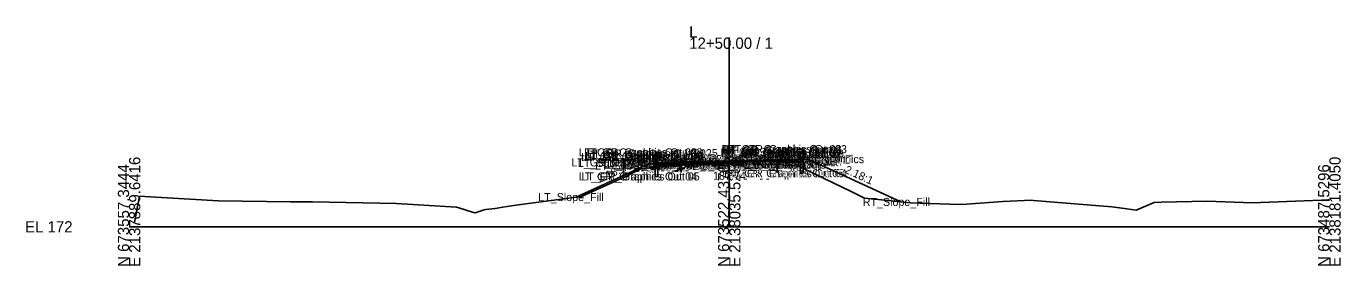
# Model space of a CAD drawing. Extents: x -26 to 5503, y -10 to 7033.
# Drawn here: x -25.7 to 302.8, y 3490.3 to 3550 of the extents above; entities that cross this region are included whole.
import ezdxf

# ---------------------------------------------------------------- set-up
doc = ezdxf.new("R2010")
doc.units = 0
for name, color, linetype in [('Default', 7, 'Continuous'), ('Exist CMT Pavement', 7, 'Continuous'), ('Exist Cross Section Cell', 7, 'Continuous'), ('Exist XS Center Line Elevation Label', 7, 'Continuous'), ('Exist XS Ground Line', 7, 'Continuous'), ('Prop CMT Guardrail Graphics', 7, 'Continuous'), ('Prop CMT Pvmt Course 1', 7, 'Continuous'), ('Prop CMT Pvmt Course 1 Wedge', 7, 'Continuous'), ('Prop CMT Pvmt Course 2', 7, 'Continuous'), ('Prop CMT Pvmt Course 2 Wedge', 7, 'Continuous'), ('Prop CMT Pvmt Course 3', 7, 'Continuous'), ('Prop CMT Pvmt Course 3 Wedge', 7, 'Continuous'), ('Prop CMT Pvmt Surface', 7, 'Continuous'), ('Prop CMT Pvmt Surface Shoulder', 7, 'Continuous'), ('Prop CMT Pvmt Wedge Surface 1', 7, 'Continuous'), ('Prop CMT Pvmt Wedge Surface 2', 7, 'Continuous'), ('Prop CMT Pvmt Wedge Surface 3', 7, 'Continuous'), ('Prop CMT Shld Paved Course 1', 7, 'Continuous'), ('Prop CMT Shld Paved Course 2', 7, 'Continuous'), ('Prop CMT Shld Paved Course 3', 7, 'Continuous'), ('Prop CMT Slope Grass', 7, 'Continuous'), ('Prop CMT Subgrade Earthwork', 7, 'Continuous'), ('Prop XS Earthwork Shape', 7, 'Continuous'), ('Prop XS EOT Tick Mark', 7, 'Continuous'), ('Prop XS SE Text', 7, 'Continuous'), ('Prop XS Side Slope Text', 7, 'Continuous'), ('Prop XS Wedging', 7, 'Continuous')]:
    doc.layers.add(name, color=color, linetype=linetype)

msp = doc.modelspace()

# ---------------------------------------------------------------- linework, layer by layer
at = {"layer": 'Exist CMT Pavement'}
for points in [[(150, 3515.74), (148.67, 3515.7), (144.01, 3515.58), (139.34, 3515.45), (138.01, 3515.42)], [(150, 3515.74), (151.33, 3515.71), (155.99, 3515.63), (160.66, 3515.54), (161.99, 3515.51)]]:
    msp.add_lwpolyline(points, dxfattribs=at)
at = {"layer": 'Exist Cross Section Cell'}
for p, q in [((150, 3500), (150, 3547.21)), ((0, 3500), (150, 3500)), ((150, 3500), (300, 3500))]:
    msp.add_line(p, q, dxfattribs=at)
at = {"layer": 'Exist XS Ground Line'}
for p, q in [((136.04, 3515.3), (137.15, 3515.41)), ((137.15, 3515.41), (138.35, 3515.42)), ((138.35, 3515.42), (149.93, 3515.74)), ((149.93, 3515.74), (157.89, 3515.59)), ((157.89, 3515.59), (162.09, 3515.51)), ((162.09, 3515.51), (164.27, 3515.27)), ((113.08, 3507.59), (123.91, 3512.45)), ((123.91, 3512.45), (127.95, 3514.49)), ((127.95, 3514.49), (131.52, 3514.87)), ((131.52, 3514.87), (134.56, 3515.11)), ((134.56, 3515.11), (135.4, 3515.24)), ((135.4, 3515.24), (136.04, 3515.3)), ((164.27, 3515.27), (167.32, 3515.1)), ((167.32, 3515.1), (180.48, 3508.77)), ((180.48, 3508.77), (183.85, 3507.14)), ((1.34, 3501.13), (2.63, 3507.65)), ((2.63, 3507.65), (6.71, 3507.4)), ((6.71, 3507.4), (22.35, 3506.52)), ((22.35, 3506.52), (40.35, 3506.23)), ((40.35, 3506.23), (45.87, 3506.22)), ((45.87, 3506.22), (66.86, 3505.85)), ((66.86, 3505.85), (81.8, 3504.91)), ((96.65, 3505.39), (113.08, 3507.59)), ((183.85, 3507.14), (188.06, 3506.74)), ((188.06, 3506.74), (195.19, 3505.97)), ((195.19, 3505.97), (207.47, 3505.54)), ((207.47, 3505.54), (209.32, 3505.61)), ((209.32, 3505.61), (218.4, 3506.32)), ((218.4, 3506.32), (225.63, 3506.63)), ((225.63, 3506.63), (226.07, 3506.56)), ((226.07, 3506.56), (245.66, 3504.95)), ((251.71, 3504.19), (256.19, 3506.08)), ((256.19, 3506.08), (258, 3506.16)), ((258, 3506.16), (269.45, 3506.37)), ((269.45, 3506.37), (280.74, 3505.96)), ((280.74, 3505.96), (298.01, 3506.66)), ((298.01, 3506.66), (300, 3506.67)), ((81.8, 3504.91), (82.39, 3504.76)), ((82.39, 3504.76), (86.05, 3503.61)), ((86.05, 3503.61), (86.47, 3503.49)), ((86.47, 3503.49), (88.72, 3504.23)), ((88.72, 3504.23), (89.06, 3504.3)), ((89.06, 3504.3), (91.51, 3504.59)), ((91.51, 3504.59), (93.43, 3504.92)), ((93.43, 3504.92), (96.65, 3505.39)), ((245.66, 3504.95), (248.8, 3504.6)), ((248.8, 3504.6), (251.71, 3504.19))]:
    msp.add_line(p, q, dxfattribs=at)
at = {"layer": 'Prop CMT Guardrail Graphics'}
for points in [[(168.52, 3519.38), (167.19, 3519.38), (166.92, 3519.09)], [(166.92, 3519.09), (167.19, 3518.8)], [(167.19, 3518.8), (166.92, 3518.51)], [(168.52, 3513.38), (168.52, 3519.38)], [(131.48, 3512.57), (131.48, 3518.57)], [(131.48, 3518.57), (132.81, 3518.57), (133.08, 3518.28)], [(133.08, 3517.7), (132.81, 3517.4), (132.15, 3517.4)], [(132.15, 3517.4), (132.15, 3512.57)], [(133.08, 3518.28), (132.81, 3517.99)], [(132.81, 3517.99), (133.08, 3517.7)], [(166.92, 3518.51), (167.19, 3518.22), (167.85, 3518.22)], [(167.85, 3518.22), (167.85, 3513.38)], [(132.15, 3512.57), (131.48, 3512.57)], [(167.85, 3513.38), (168.52, 3513.38)]]:
    msp.add_lwpolyline(points, dxfattribs=at)
at = {"layer": 'Prop CMT Pvmt Course 1'}
for points in [[(150, 3516.49), (138, 3516.19)], [(138, 3516.19), (138, 3515.94)], [(138, 3515.94), (138.01, 3515.94)], [(138.01, 3516.07), (150, 3516.37)], [(138.01, 3515.94), (138.01, 3516.07)], [(150, 3516.49), (162, 3516.77)], [(161.99, 3516.64), (150, 3516.37)], [(150, 3516.37), (150, 3516.49)], [(150, 3516.37), (150, 3516.49)], [(161.99, 3516.52), (161.99, 3516.64)], [(162, 3516.52), (161.99, 3516.52)], [(162, 3516.77), (162, 3516.52)]]:
    msp.add_lwpolyline(points, dxfattribs=at)
at = {"layer": 'Prop CMT Pvmt Course 1 Wedge'}
for points in [[(150, 3516.37), (138.01, 3516.07)], [(150, 3516.37), (161.99, 3516.64)]]:
    msp.add_lwpolyline(points, dxfattribs=at)
at = {"layer": 'Prop CMT Pvmt Course 2'}
for points in [[(138.01, 3515.94), (138, 3515.94)], [(138, 3515.94), (138, 3515.74)], [(138, 3515.74), (138.01, 3515.74)], [(138.01, 3515.74), (138.01, 3515.94)]]:
    msp.add_lwpolyline(points, dxfattribs=at)
at = {"layer": 'Prop CMT Pvmt Course 2 Wedge'}
for points in [[(150, 3516.24), (138.01, 3515.94)], [(150, 3516.24), (161.99, 3516.52)]]:
    msp.add_lwpolyline(points, dxfattribs=at)
at = {"layer": 'Prop CMT Pvmt Course 3'}
for points in [[(138.01, 3515.74), (138, 3515.74)], [(138, 3515.74), (138, 3515.4)], [(138, 3515.4), (138.01, 3515.4)], [(138.01, 3515.4), (138.01, 3515.74)], [(161.99, 3516.31), (162, 3516.31)], [(161.99, 3515.98), (161.99, 3516.31)], [(162, 3515.98), (161.99, 3515.98)], [(162, 3516.31), (162, 3515.98)]]:
    msp.add_lwpolyline(points, dxfattribs=at)
at = {"layer": 'Prop CMT Pvmt Course 3 Wedge'}
for points in [[(150, 3516.04), (138.01, 3515.74)], [(150, 3516.04), (161.99, 3516.31)]]:
    msp.add_lwpolyline(points, dxfattribs=at)
at = {"layer": 'Prop CMT Pvmt Surface'}
for points in [[(150, 3516.49), (138, 3516.19)], [(150, 3516.49), (162, 3516.77)]]:
    msp.add_lwpolyline(points, dxfattribs=at)
at = {"layer": 'Prop CMT Pvmt Surface Shoulder'}
for points in [[(138, 3516.19), (133.09, 3516.07)], [(162, 3516.77), (166.91, 3516.88)]]:
    msp.add_lwpolyline(points, dxfattribs=at)
at = {"layer": 'Prop CMT Pvmt Wedge Surface 1'}
for points in [[(138.01, 3516.19), (138, 3516.19)], [(150, 3516.37), (138.01, 3516.07)], [(138.01, 3516.07), (138.01, 3516.19)], [(150, 3516.37), (161.99, 3516.64)], [(161.99, 3516.64), (161.99, 3516.77)], [(161.99, 3516.77), (162, 3516.77)]]:
    msp.add_lwpolyline(points, dxfattribs=at)
at = {"layer": 'Prop CMT Pvmt Wedge Surface 2'}
for points in [[(150, 3516.24), (138.01, 3515.94), (138, 3515.94)], [(138, 3515.94), (138, 3516.19)], [(150, 3516.24), (161.99, 3516.52), (162, 3516.52)], [(162, 3516.52), (162, 3516.77)]]:
    msp.add_lwpolyline(points, dxfattribs=at)
at = {"layer": 'Prop CMT Pvmt Wedge Surface 3'}
for points in [[(138, 3515.74), (138, 3516.19)], [(150, 3516.04), (138.01, 3515.74), (138, 3515.74)], [(150, 3516.04), (161.99, 3516.31), (162, 3516.31)], [(162, 3516.31), (162, 3516.77)]]:
    msp.add_lwpolyline(points, dxfattribs=at)
at = {"layer": 'Prop CMT Shld Paved Course 1'}
for points in [[(138, 3516.19), (133.09, 3516.07), (132.84, 3515.81)], [(132.84, 3515.81), (138, 3515.94)], [(138, 3515.94), (138, 3516.19)], [(162, 3516.77), (166.91, 3516.88), (167.15, 3516.64)], [(162, 3516.52), (162, 3516.77)], [(167.15, 3516.64), (162, 3516.52)]]:
    msp.add_lwpolyline(points, dxfattribs=at)
at = {"layer": 'Prop CMT Shld Paved Course 2'}
for points in [[(138, 3515.94), (132.84, 3515.81), (132.62, 3515.6)], [(132.62, 3515.6), (138, 3515.74)], [(138, 3515.74), (138, 3515.94)], [(162, 3516.52), (167.15, 3516.64), (167.36, 3516.43)], [(162, 3516.31), (162, 3516.52)], [(167.36, 3516.43), (162, 3516.31)]]:
    msp.add_lwpolyline(points, dxfattribs=at)
at = {"layer": 'Prop CMT Shld Paved Course 3'}
for points in [[(132.62, 3515.6), (132.28, 3515.26)], [(132.28, 3515.26), (138, 3515.4)], [(138, 3515.74), (132.62, 3515.6)], [(132.62, 3515.6), (132.62, 3515.6)], [(138, 3515.4), (138, 3515.74)], [(162, 3516.31), (167.36, 3516.43)], [(162, 3515.98), (162, 3516.31)], [(167.68, 3516.11), (162, 3515.98)], [(167.36, 3516.43), (167.36, 3516.43)], [(167.36, 3516.43), (167.68, 3516.11)]]:
    msp.add_lwpolyline(points, dxfattribs=at)
at = {"layer": 'Prop CMT Slope Grass'}
for points in [[(130.08, 3515.83), (111.76, 3507.42)], [(133.08, 3516.07), (130.08, 3515.83)], [(133.09, 3516.07), (133.08, 3516.07)], [(166.91, 3516.88), (166.92, 3516.88)], [(166.92, 3516.88), (169.92, 3516.77)], [(169.92, 3516.77), (192.91, 3506.21)]]:
    msp.add_lwpolyline(points, dxfattribs=at)
at = {"layer": 'Prop CMT Subgrade Earthwork'}
for points in [[(132.28, 3515.26), (131.59, 3515.95)], [(138, 3515.4), (132.28, 3515.26)], [(138.01, 3515.4), (138, 3515.4)], [(138.01, 3515.4), (138.01, 3515.42)], [(161.99, 3515.98), (161.99, 3515.51)], [(161.99, 3515.98), (162, 3515.98)], [(162, 3515.98), (167.68, 3516.11)], [(167.68, 3516.11), (168.4, 3516.83)]]:
    msp.add_lwpolyline(points, dxfattribs=at)
at = {"layer": 'Prop XS Earthwork Shape'}
for points in [[(131.59, 3515.95), (130.08, 3515.83), (111.76, 3507.42), (113.08, 3507.59), (123.91, 3512.45), (127.95, 3514.49), (131.52, 3514.87), (134.56, 3515.11), (135.4, 3515.24), (136.04, 3515.3), (136.83, 3515.37), (132.28, 3515.26)], [(139.34, 3515.45), (138, 3515.4), (136.83, 3515.37), (137.15, 3515.41), (138.35, 3515.42)], [(149.93, 3515.74), (150, 3515.74), (148.67, 3515.7)], [(155.99, 3515.63), (157.89, 3515.59), (160.66, 3515.54)], [(168.4, 3516.83), (169.92, 3516.77), (192.91, 3506.21), (188.06, 3506.74), (183.85, 3507.14), (180.48, 3508.77), (167.32, 3515.1), (164.27, 3515.27), (162.09, 3515.51), (161.99, 3515.51), (161.99, 3515.98), (167.68, 3516.11)]]:
    msp.add_lwpolyline(points, close=True, dxfattribs=at)
at = {"layer": 'Prop XS EOT Tick Mark'}
for points in [[(138, 3516.19), (138, 3517.19)], [(138, 3516.19), (138, 3517.19)], [(162, 3516.77), (162, 3517.77)], [(162, 3516.77), (162, 3517.77)]]:
    msp.add_lwpolyline(points, dxfattribs=at)
at = {"layer": 'Prop XS Wedging'}
for p, q in [((138, 3517.19), (138, 3513.55)), ((162, 3517.77), (162, 3513.52))]:
    msp.add_line(p, q, dxfattribs=at)

# ---------------------------------------------------------------- texts
at = {"layer": 'Default'}
for s, height, p in [('LT_GR_Graphics Out 03', 2, (112.38, 3517.57)), ('LT_GR_Graphics Out 02', 2, (113.71, 3517.57)), ('LT_GR_Graphics Out 09', 2, (113.71, 3516.99)), ('LT_GR_Graphics Out 08', 2, (113.98, 3516.7)), ('LT_GR_Graphics Out 01', 2, (114.55, 3517.28)), ('RT_GR_Graphics Out 08', 2, (147.77, 3517.51)), ('RT_GR_Graphics Out 02', 2, (148.04, 3518.38)), ('RT_GR_Graphics Out 09', 2, (148.04, 3517.8)), ('RT_GR_Graphics Out 07', 2, (148.04, 3517.22)), ('RT_GR_Graphics Out 01', 2, (148.33, 3518.09)), ('RT_GR_Graphics Out 06', 2, (148.66, 3517.22)), ('RT_GR_Graphics Out 03', 2, (149.37, 3518.38)), ('RT_TM_OEOT', 2, (152.9, 3516.77)), ('LT_GS_OS_GR_Face_Graphics', 2, (110.54, 3515.07)), ('LT_Sub_Trench_Out_DLT', 2, (112.16, 3514.95)), ('LT_GR_Graphics Out 06', 2, (113, 3516.4)), ('LT_GR_Graphics Out 07', 2, (113.71, 3516.4)), ('LT_Sub_Trench_Out', 2, (116.49, 3514.26)), ('LT_PS3_Shelf_Out', 2, (118.61, 3514.6)), ('LT_GS_OS_CTL', 2, (119.45, 3514.83)), ('LT_PS3_OEOP', 2, (122.86, 3514.6)), ('LT_PV_Sub_Tie_Out', 2, (122.96, 3514.42)), ('LT_PS2_OEOP', 2, (123.07, 3514.81)), ('LT_PS1_OEOP', 2, (123.9, 3515.07)), ('LT_PV1_OEEOP_Null', 2, (124.47, 3515.19)), ('LT_PV_EG_TestPt3', 2, (124.85, 3514.45)), ('LT_PV_OEEOP_EG', 2, (125.55, 3514.42)), ('LT_PV1_OEEOP_W', 2, (125.99, 3515.07)), ('LT_Sub_OEEOP', 2, (127.22, 3514.4)), ('LT_PV2_OEEOP', 2, (127.32, 3514.94)), ('LT_PV3_OEEOP', 2, (127.32, 3514.74)), ('LT_Sub_OEOT', 2, (128.08, 3514.4)), ('LT_PV2_OEOT', 2, (128.17, 3514.94)), ('LT_PV3_OEOT', 2, (128.17, 3514.74)), ('LT_PV1_OEOT', 2, (128.74, 3515.19)), ('LT_TM_OEOT', 2, (128.94, 3516.19)), ('LT_PV_EG_TestPt2', 2, (129.52, 3514.58)), ('LT_PV_EG_TestPt1', 2, (134.75, 3514.7)), ('RT_PV_EG_TestPt1', 2, (137.36, 3514.71)), ('PV_EPGL_EG', 2, (141.24, 3514.74)), ('RT_PV_EG_TestPt2', 2, (141.46, 3514.63)), ('PV2_PGL_W', 2, (142.02, 3515.24)), ('PV3_PGL_W', 2, (142.02, 3515.04)), ('PV1_PGL_W', 2, (142.58, 3515.37)), ('RT_GS_OS_GR_Face_Graphics', 2, (144.33, 3515.88)), ('PV1_PGL', 2, (144.47, 3515.49)), ('RT_PV_EG_TestPt3', 2, (146.12, 3514.54)), ('RT_PV_Sub_Tie_Out', 2, (146.89, 3514.51)), ('RT_PV1_OEEOP_Null', 2, (148.4, 3515.77)), ('RT_Sub_Trench_Out_DLT', 2, (148.92, 3515.83)), ('RT_PV_OEEOP_EG', 2, (149.48, 3514.51)), ('RT_PV1_OEEOP_W', 2, (149.93, 3515.64)), ('RT_PV1_OEEOP_W', 2, (149.93, 3515.64)), ('RT_Sub_OEEOP', 2, (151.16, 3514.98)), ('RT_Sub_OEEOP', 2, (151.16, 3514.98)), ('RT_PV2_OEEOP', 2, (151.25, 3515.52)), ('RT_PV2_OEEOP', 2, (151.25, 3515.52)), ('RT_PV3_OEEOP', 2, (151.25, 3515.31)), ('RT_PV3_OEEOP', 2, (151.25, 3515.31)), ('RT_Sub_Trench_Out', 2, (151.84, 3515.11)), ('RT_Sub_OEOT', 2, (152.03, 3514.98)), ('RT_PV2_OEOT', 2, (152.13, 3515.52)), ('RT_PV3_OEOT', 2, (152.13, 3515.31)), ('RT_PV1_OEOT', 2, (152.69, 3515.77)), ('RT_PS3_Shelf_Out', 2, (153.29, 3515.43)), ('RT_PS2_OEOP', 2, (157.34, 3515.64)), ('RT_PS3_OEOP', 2, (157.54, 3515.43)), ('RT_PS1_OEOP', 2, (157.66, 3515.88)), ('RT_GS_OS_CTL', 2, (159.24, 3515.77)), ('LT_GR_Graphics Out 04', 2, (112.38, 3511.57)), ('LT_GR_Graphics Out 05', 2, (113.04, 3511.57)), ('RT_GR_Graphics Out 05', 2, (148.7, 3512.38)), ('RT_GR_Graphics Out 04', 2, (149.37, 3512.38)), ('LT_Slope_Fill', 2, (102.27, 3506.42)), ('RT_Slope_Fill', 2, (183.38, 3505.21)), ('-', 0.0001, (0, 3500))]:
    msp.add_text(s, height=height, dxfattribs=at).set_placement(p)
at = {"layer": 'Exist Cross Section Cell'}
for s, p in [('L', (140, 3547.21)), ('12+50.00 / 1', (140, 3544.41)), ('EL 172', (-26, 3498.6))]:
    msp.add_text(s, height=2.8, dxfattribs=at).set_placement(p)
for s, p in [('N 673557.3444', (0, 3490)), ('E 2137889.6416', (2.8, 3490)), ('N 673522.4370', (150, 3490)), ('E 2138035.5233', (152.8, 3490)), ('N 673487.5296', (300, 3490)), ('E 2138181.4050', (302.8, 3490))]:
    msp.add_text(s, height=2.8, rotation=90, dxfattribs=at).set_placement(p)
at = {"layer": 'Exist XS Center Line Elevation Label'}
msp.add_text('187.74', height=2, dxfattribs=at).set_placement((145.96, 3511.74))
at = {"layer": 'Prop XS SE Text'}
for s, rotation, p in [('0.025', 1.4321, (140.48, 3517.26)), ('0.023', 1.3176, (152.49, 3517.55))]:
    msp.add_text(s, height=2, rotation=rotation, dxfattribs=at).set_placement(p)
at = {"layer": 'Prop XS Side Slope Text'}
for rotation, p in [(24.663, (117.57, 3510.91)), (335.337, (178.69, 3513.57))]:
    msp.add_text('2.18:1', height=2, rotation=rotation, dxfattribs=at).set_placement(p)

doc.saveas('drawing.dxf')
